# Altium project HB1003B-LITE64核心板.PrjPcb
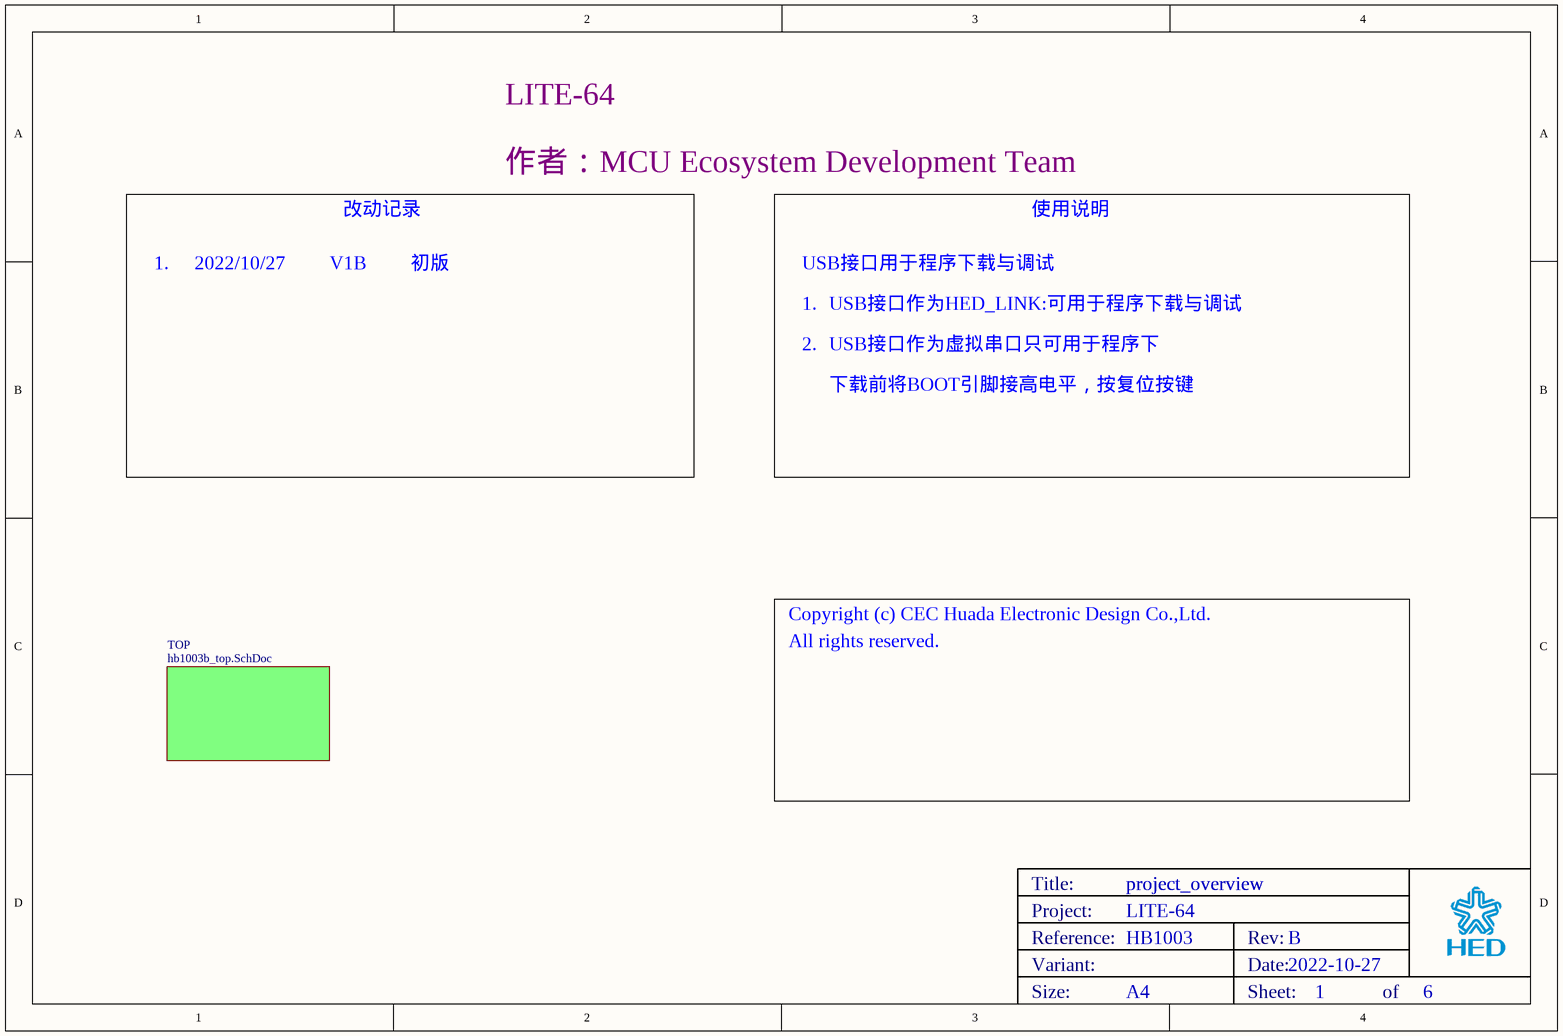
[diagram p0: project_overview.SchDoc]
Board_Assembly_Revision: 01; Board_Name: LITE-64; Board_PCB_Revision: B; Board_Reference: HB1003
6 sheets, 120 parts. Net scope: global (net labels, ports and power ports of the same name join across sheets).
Board file: hb1003b.PcbDoc
Sheets:
  project_overview.SchDoc
    TOP = hb1003b_top.SchDoc
      hed_link = hed_link.SchDoc
      arduino_extension_interfaces = arduino_extension_interfaces.SchDoc
      MCU = mcu.SchDoc
      power = power.SchDoc

## Sheet project_overview.SchDoc: project_overview
size A4; Date: 2022-10-27; DrawnBy: liuchao; SheetNumber: 1; SheetTotal: 6

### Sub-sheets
TOP = hb1003b_top.SchDoc: no entries

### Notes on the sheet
- 作者：MCU Ecosystem Development Team
- 改动记录
- 使用说明
- 1.
- 2022/10/27
- V1B
- 初版
- USB接口用于程序下载与调试
- USB接口作为HED_LINK:可用于程序下载与调试
- 2.
- USB接口作为虚拟串口只可用于程序下
- 下载前将BOOT引脚接高电平，按复位按键
- Copyright (c) CEC Huada Electronic Design Co.,Ltd.
- All rights reserved.

## Sheet hb1003b_top.SchDoc: top
size A4; Date: 2022-10-27; DrawnBy: liuchao; SheetNumber: 2; SheetTotal: 6
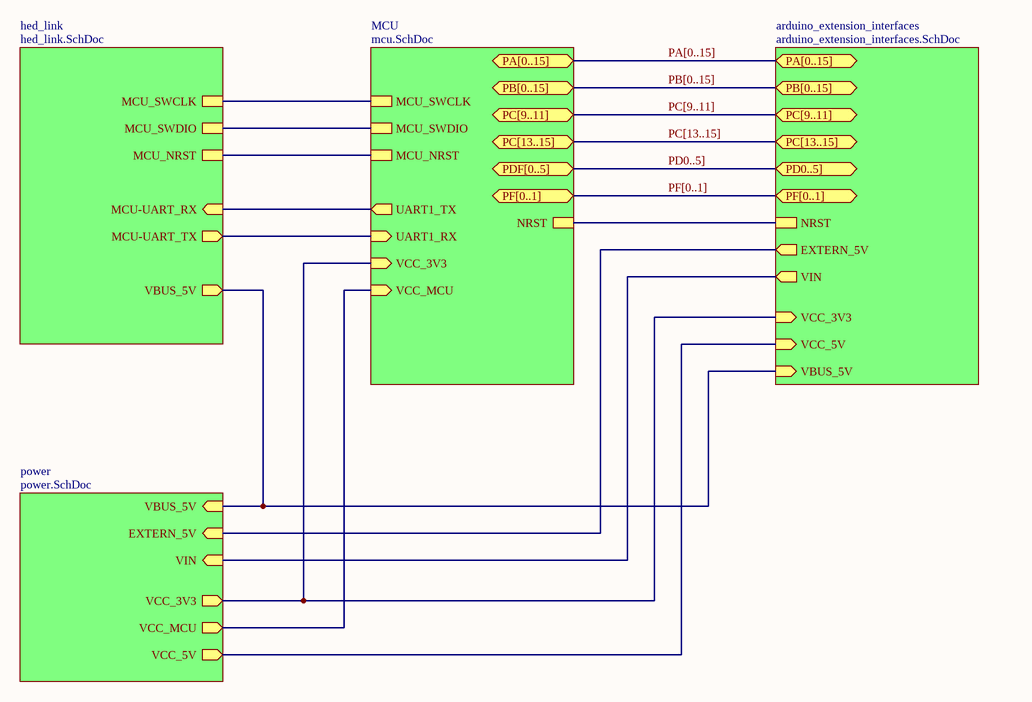
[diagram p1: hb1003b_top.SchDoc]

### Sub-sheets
arduino_extension_interfaces = arduino_extension_interfaces.SchDoc: NRST, VBUS_5V (in), EXTERN_5V (out), VIN (out), VCC_3V3 (in), VCC_5V (in)
hed_link = hed_link.SchDoc: MCU_SWDIO, MCU_SWCLK, MCU_NRST, MCU-UART_RX (in), MCU-UART_TX (out), VBUS_5V (out)
MCU = mcu.SchDoc: UART1_RX (in), UART1_TX (out), MCU_SWCLK, MCU_SWDIO, MCU_NRST, VCC_3V3 (in), VCC_MCU (in), NRST
power = power.SchDoc: VCC_MCU (out), VBUS_5V (in), EXTERN_5V (in), VIN (in), VCC_3V3 (out), VCC_5V (out)

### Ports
PA[0..15], PB[0..15], PC[9..11], PC[13..15], PD0..5], PDF[0..5], PF[0..1]

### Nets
(unnamed): sheet hed_link/MCU_SWDIO, sheet MCU/MCU_SWDIO
(unnamed): sheet hed_link/MCU_SWCLK, sheet MCU/MCU_SWCLK  [a separate net that carries the same name]
(unnamed): sheet hed_link/MCU_NRST, sheet MCU/MCU_NRST  [a separate net that carries the same name]
(unnamed): sheet hed_link/MCU-UART_RX, sheet MCU/UART1_TX  [a separate net that carries the same name]
(unnamed): sheet hed_link/MCU-UART_TX, sheet MCU/UART1_RX  [a separate net that carries the same name]
(unnamed): sheet hed_link/VBUS_5V, sheet arduino_extension_interfaces/VBUS_5V, sheet power/VBUS_5V  [a separate net that carries the same name]
(unnamed): sheet arduino_extension_interfaces/NRST, sheet MCU/NRST  [a separate net that carries the same name]
(unnamed): sheet arduino_extension_interfaces/EXTERN_5V, sheet power/EXTERN_5V  [a separate net that carries the same name]
(unnamed): sheet arduino_extension_interfaces/VIN, sheet power/VIN  [a separate net that carries the same name]
(unnamed): sheet arduino_extension_interfaces/VCC_3V3, sheet MCU/VCC_3V3, sheet power/VCC_3V3  [a separate net that carries the same name]
(unnamed): sheet arduino_extension_interfaces/VCC_5V, sheet power/VCC_5V  [a separate net that carries the same name]
(unnamed): sheet MCU/VCC_MCU, sheet power/VCC_MCU  [a separate net that carries the same name]

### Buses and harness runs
bus PA[0..15] = port PA[0..15]
bus PB[0..15] = port PB[0..15]
bus PC[9..11] = port PC[9..11]
bus PC[13..15] = port PC[13..15]
bus PD0..5] = port PD0..5] = port PDF[0..5]
bus PF[0..1] = port PF[0..1]

## Sheet hed_link.SchDoc: HED_Link
size A4; Date: 2022-10-27; DrawnBy: liuchao; SheetNumber: 6; SheetTotal: 6
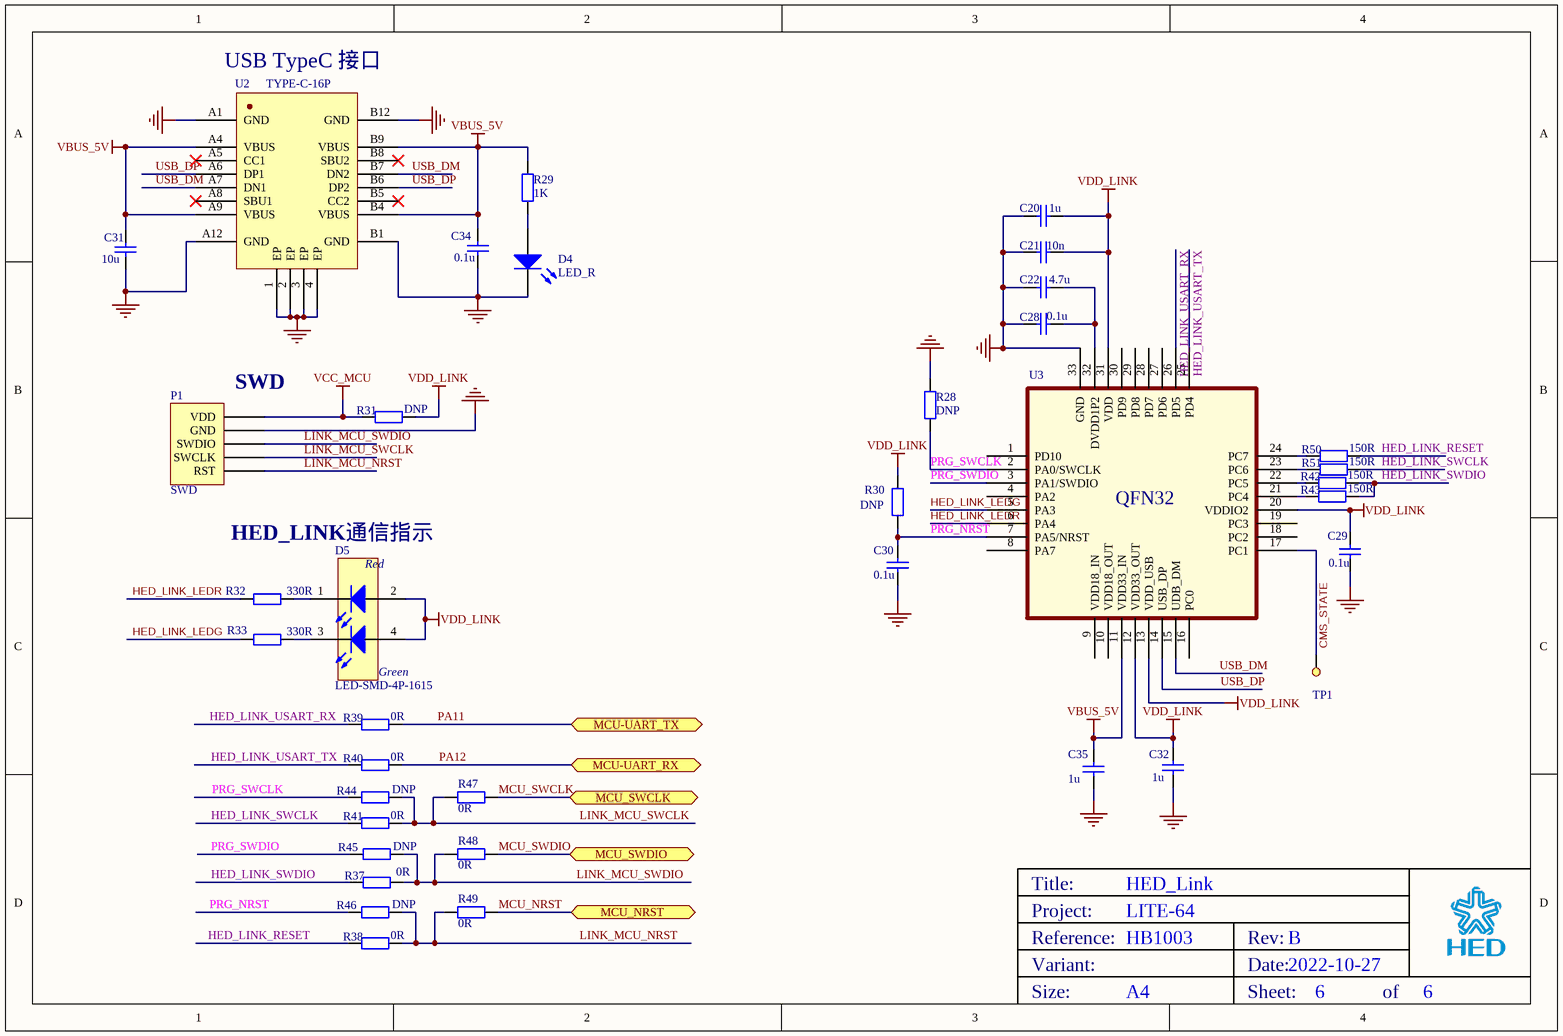
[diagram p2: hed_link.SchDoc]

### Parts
C20  1u  [0603]
C21  10n  [0603]
C22  4.7u  [0603]
C28  0.1u  [0603]
C29  0.1u  [0603]
C30  0.1u  [0603]
C31  10u  [0603]
C32  1u  [0603]
C34  0.1u  [0603]
C35  1u  [0603]
D4  LED_R  [0603 - p]
D5  Manufacturer_Part_Number: LED-SMD-4P-1615  [LED-SMD_4P_1615]  (hidden comment: LD_BICOLOR_CMS)
P1  SWD  [HED_5_4_2.5]
R28  DNP  [0603]
R29  1K  [0603]
R30  DNP  [0603]
R31  DNP  [0603]
R32  330R  [0603]
R33  330R  [0603]
R37  0R  [0603]
R38  0R  [0603]
R39  0R  [0603]
R40  0R  [0603]
R41  0R  [0603]
R42  150R  [0603]
R43  150R  [0603]
R44  DNP  [0603]
R45  DNP  [0603]
R46  DNP  [0603]
R47  0R  [0603]
R48  0R  [0603]
R49  0R  [0603]
R50  150R  [0603]
R51  150R  [0603]
TP1  TEST_POINT  [TEST_POINT]  (value not drawn)
U2  TYPE-C-16P  [HED-KH-TYPE-C-16P]
U3  MCU  [HED-QFN-32_5x5x05P]  (value not drawn)

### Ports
MCU-UART_RX (bidir), MCU-UART_TX (bidir), MCU_NRST, MCU_SWCLK, MCU_SWDIO

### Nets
GND: C20.1 C21.1 C22.1 C28.1 C29.2 C30.2 C31.1 C32.2 C34.1 C35.2 D4.2(K) P1.2(GND) R28.2 U2.1(EP) U2.2(EP) U2.3(EP) U2.4(EP) U2.A1(GND) U2.A12(GND) U2.B1(GND) U2.B12(GND) U3.33(GND)
VBUS_5V: C31.2 C34.2 C35.1 R29.1 U2.A4(VBUS) U2.A9(VBUS) U2.B4(VBUS) U2.B9(VBUS) U3.11(VDD33_IN)
VCC_MCU: P1.1(VDD) R31.1
VDD_LINK: C20.2 C21.2 C29.1 C32.1 D5.2(RED_cathode) D5.4(YellowGreen_anode) R30.1 R31.2 U3.12(VDD33_OUT) U3.13(VDD_USB) U3.20(VDDIO2) U3.31(VDD)
CMS_STATE: TP1.1 U3.17(PC1)
HED_LINK_LEDG: R33.1 U3.5(PA3)
HED_LINK_LEDR: R32.1 U3.6(PA4)
HED_LINK_RESET: R38.1 R50.2
HED_LINK_SWCLK: R41.1 R51.2
HED_LINK_SWDIO: R37.1 R42.2 R43.2
HED_LINK_USART_RX: R39.1 U3.26(PD5)
HED_LINK_USART_TX: R40.1 U3.25(PD4)
LINK_MCU_NRST: P1.5(RST) R38.2 R46.2 R49.2
LINK_MCU_SWCLK: P1.4(SWCLK) R41.2 R44.2 R47.2
LINK_MCU_SWDIO: P1.3(SWDIO) R37.2 R45.2 R48.2
MCU_NRST: R49.1 ; port MCU_NRST
MCU_SWCLK: R47.1 ; port MCU_SWCLK
MCU_SWDIO: R48.1 ; port MCU_SWDIO
PA11: R39.2 ; port MCU-UART_TX
PA12: R40.2 ; port MCU-UART_RX
PRG_NRST: C30.1 R30.2 R46.1 U3.7(PA5/NRST)
PRG_SWCLK: R28.1 R44.1 U3.2(PA0/SWCLK)
PRG_SWDIO: R45.1 U3.3(PA1/SWDIO)
USB_DM: U2.A7(DN1) U2.B7(DN2) U3.15(UDB_DM)
USB_DP: U2.A6(DP1) U2.B6(DP2) U3.14(USB_DP)
NetC22_2: C22.2 C28.2 U3.32(DVDD1P2)
NetD4_1: D4.1(A) R29.2
NetD5_1: D5.1(Red_anode) R32.2
NetD5_3: D5.3(YellowGreen_cathode) R33.2
NetR42_1: R42.1 U3.22(PC5)
NetR43_1: R43.1 U3.21(PC4)
NetR50_1: R50.1 U3.24(PC7)
NetR51_1: R51.1 U3.23(PC6)

Not connected (* = marked no-connect by the designer): U2 A5(CC1)* A8(SBU1)* B5(CC2)* B8(SBU2)*; U3 1(PD10) 4(PA2) 8(PA7) 9(VDD18_IN) 10(VDD18_OUT) 16(PC0) 18(PC2) 19(PC3) 27(PD6) 28(PD7) 29(PD8) 30(PD9)

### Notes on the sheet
- (near U2) USB TypeC 接口
- (near P1) SWD
- HED_LINK通信指示

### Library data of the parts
C20-C22 C28-C30 C32 C35 = MCD-00211: Capacitor, MLCC, 100nF, 16V, X7R, 10%, 0603, T=0,8mm; Manufacturer_Part_Number: CC0603KRX7R7BB104; Manufacturer: YAGEO; Provided_By: Subcon; Initial_Board_Reference: mb1319
C31 = 0603 4.7uF 10% 16V: 贴片电容
C34 = 0603 100nF 10% 50V: 贴片电容
D4 = LED3: Typical BLUE SiC LED; sold/unsold: sold
D5 = LD_BICOLOR_CMS: LED Bicolor; Internal_Part_Number: MCD-00051; Part_Type: Display; Manufacturer: AVAGO TECHNOLOGIES; Alternate_Manufacturer_Part_Number: LE-RGW35280; Alternate_Manufacturer: EVERLUCK; ECCN_US: EAR99; ECCN_EU: NEC; Provided_By: Subcon; Initial_Board_Reference: mb1274
R28 R44-R49 = Res: 贴片电阻; Value: 1K
R29 = Res2: 贴片电阻
R30-R33 R37-R43 R50 R51 = Res2: 贴片电阻; Value: 1K
U2 = KH-TYPE-C-16P: TYPE-C USB接口
U3 = CIU98-H

## Sheet arduino_extension_interfaces.SchDoc: arduino interface
size A4; Date: 2022-10-27; DrawnBy: liuchao; SheetNumber: 5; SheetTotal: 6
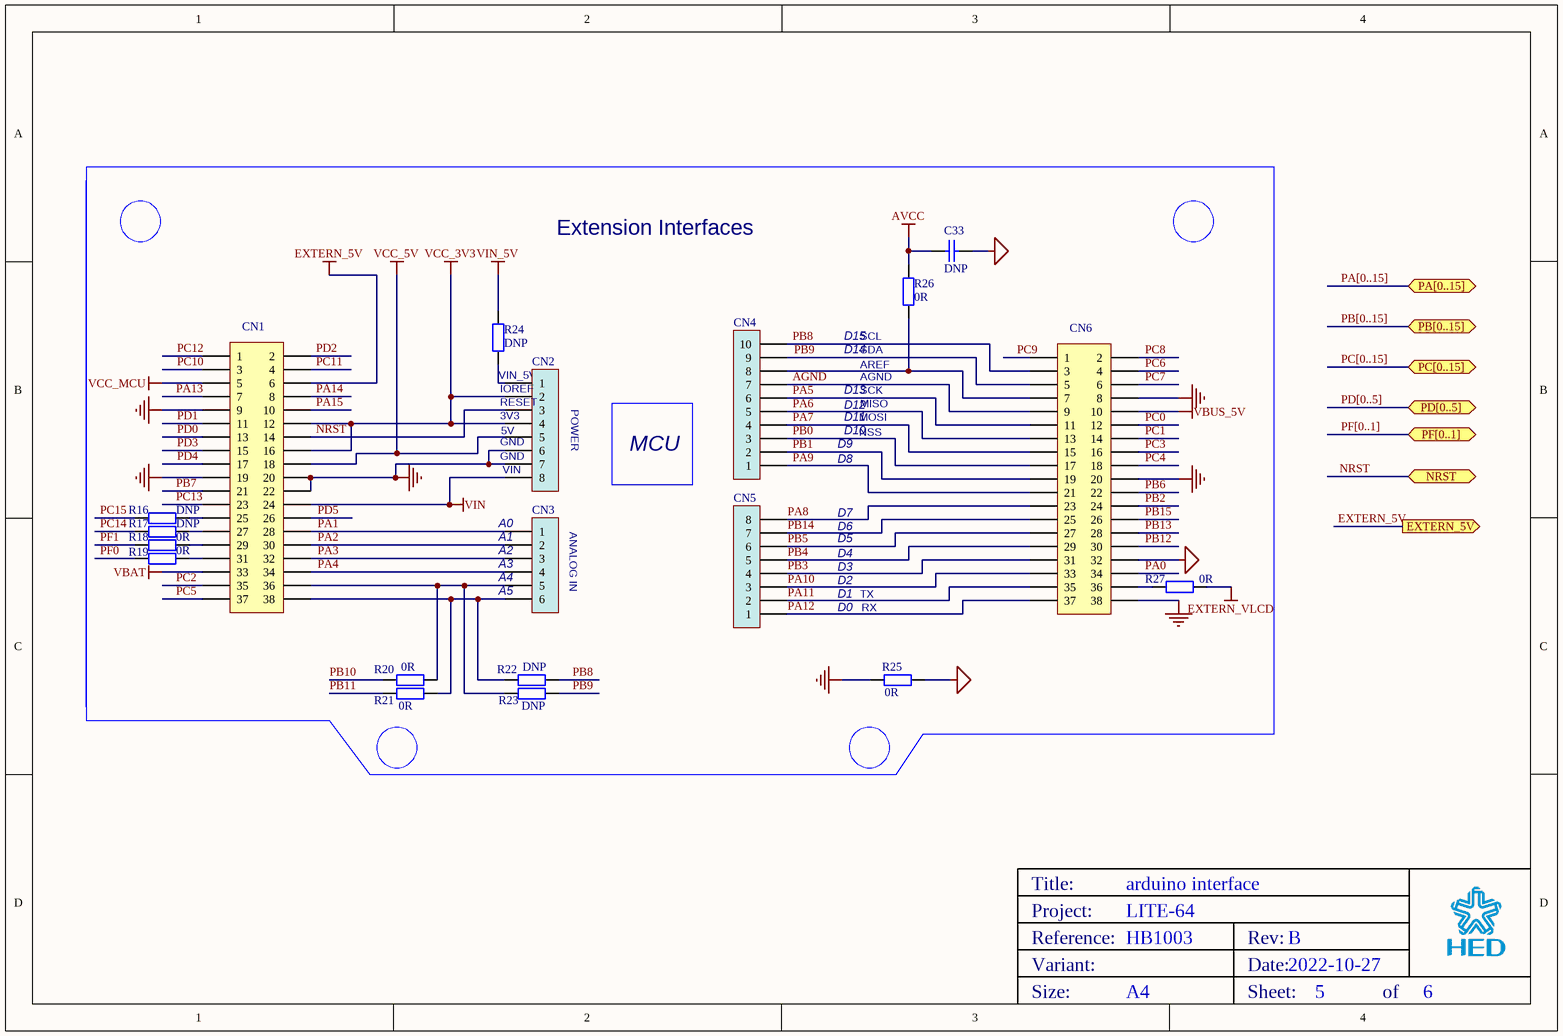
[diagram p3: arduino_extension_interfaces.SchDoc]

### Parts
C33  DNP  [0603]
CN1  Header 23x2  [HEADER_1X19_2.54]  (value not drawn)
CN2  Socket 8x1  [HEADER_1X8_2.54]  (value not drawn)
CN3  Socket 6x1  [HEADER_1X6-2.54]  (value not drawn)
CN4  Socket 10x1  [HEADER_1X10_2.54]  (value not drawn)
CN5  Socket 8x1  [HEADER_1X8_2.54]  (value not drawn)
CN6  Header 23x2  [HEADER_1X19_2.54]  (value not drawn)
R16  DNP  [0603]
R17  DNP  [0603]
R18  0R  [0603]
R19  0R  [0603]
R20  0R  [0603]
R21  0R  [0603]
R22  DNP  [0603]
R23  DNP  [0603]
R24  DNP  [0603]
R25  0R  [0603]
R26  0R  [0603]
R27  0R  [0603]

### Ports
EXTERN_5V (out), NRST, PA[0..15] (bidir), PB[0..15] (bidir), PC[0..15] (bidir), PD[0..5], PF[0..1] (bidir)

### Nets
AGND: C33.1 CN4.7 CN6.9 CN6.32 R25.1
EXTERN_5V: CN1.6 ; port EXTERN_5V
EXTERN_VLCD: R27.1
GND: CN1.9 CN1.19 CN1.20 CN1.22 CN2.6 CN2.7 CN6.8 CN6.20 CN6.38 R25.2
PA0: C33.2 CN6.34 R26.1  [also labelled AVCC]
VBAT: CN1.33
VBUS_5V: CN6.10
VCC_3V3: CN1.12 CN1.16 CN2.2 CN2.4
VCC_5V: CN1.18 CN2.5
VCC_MCU: CN1.5
VIN: CN1.24 CN2.8
VIN_5V: R24.1
NRST: CN1.14 CN2.3 ; port NRST
PA1: CN1.28 CN3.1
PA2: CN1.30 CN3.2
PA3: CN1.32 CN3.3
PA4: CN1.34 CN3.4
PA5: CN4.6 CN6.11
PA6: CN4.5 CN6.13
PA7: CN4.4 CN6.15
PA8: CN5.8 CN6.23
PA9: CN4.1 CN6.21
PA10: CN5.3 CN6.33
PA11: CN5.2 CN6.35
PA12: CN5.1 CN6.37
PA13: CN1.7
PA14: CN1.8
PA15: CN1.10
PB0: CN4.3 CN6.17
PB1: CN4.2 CN6.19
PB2: CN6.24
PB3: CN5.4 CN6.31
PB4: CN5.5 CN6.29
PB5: CN5.6 CN6.27
PB6: CN6.22
PB7: CN1.21
PB8: CN4.10 CN6.3 R22.1
PB9: CN4.9 CN6.5 R23.1
PB10: R20.2
PB11: R21.2
PB12: CN6.30
PB13: CN6.28
PB14: CN5.7 CN6.25
PB15: CN6.26
PC0: CN6.12
PC1: CN6.14
PC2: CN1.35
PC3: CN6.16
PC4: CN6.18
PC5: CN1.37
PC6: CN6.4
PC7: CN6.6
PC8: CN6.2
PC9: CN6.1
PC10: CN1.3
PC11: CN1.4
PC12: CN1.1
PC13: CN1.23
PC14: R17.2
PC15: R16.2
PD0: CN1.13
PD1: CN1.11
PD2: CN1.2
PD3: CN1.15
PD4: CN1.17
PD5: CN1.26
PF0: R19.2
PF1: R18.2
NetCN1_25: CN1.25 R16.1
NetCN1_27: CN1.27 R17.1
NetCN1_29: CN1.29 R18.1
NetCN1_31: CN1.31 R19.1
NetCN1_36: CN1.36 CN3.5 R20.1 R23.2
NetCN1_38: CN1.38 CN3.6 R21.1 R22.2
NetCN2_1: CN2.1 R24.2
NetCN4_8: CN4.8 CN6.7 R26.2
NetCN6_36: CN6.36 R27.2

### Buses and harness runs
bus PA[0..15] = port PA[0..15]
bus PB[0..15] = port PB[0..15]
bus PC[0..15] = port PC[0..15]
bus PD[0..5] = port PD[0..5]
bus PF[0..1] = port PF[0..1]

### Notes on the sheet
- Extension Interfaces
- (near CN2) VIN_5V
- D14
- D15
- (near R26) SDA
- (near R26) SCL
- AREF
- AGND
- (near CN2) IOREF
- (near CN2) 3V3
- (near CN2) GND
- (near CN2) RESET
- (near CN2) 5V
- (near CN2) POWER
- D9
- D10
- D13
- D12
- D11
- MOSI
- NSS
- MISO
- SCK
- (near CN2) VIN
- MCU
- D7
- D8
- (near CN3) A0
- (near CN3) A1
- (near CN3) A2
- (near CN3) A3
- (near CN3) A4
- (near CN3) ANALOG IN
- D2
- D4
- D3
- D5
- D6
- (near CN3) A5
- D0
- D1
- TX
- RX

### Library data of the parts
C33 = MCD-00211: as C20 on sheet hed_link
CN1 CN6 = Header 19x2: Header, 19x2, 2,54mm, VR, TH, Height 5.84mm/10.16mm; Internal_Part_Number: MCD-00213; Manufacturer: SAMTEC; Part_Type: Connector; Manufacturer_Part_Number: TSW-119-09-x-D1; Provided_By: Subcon; Initial_Board_Reference: mb1319
CN2 = MCD-00261: Socket, 8x1, 2.54mm, VR, TH, Height 8.51mm/10mm; Manufacturer_Part_Number: SSW-108-03-x-S; Manufacturer: SAMTEC; Part_Type: Connector; Provided_By: Subcon; Initial_Board_Reference: mb1319
CN3 = MCD-00260: Socket, 6x1, 2.54mm, VR, TH, Height 8.51mm/10mm; Part_Type: Connector; Manufacturer_Part_Number: SSW-106-03-x-S; Manufacturer: SAMTEC; Provided_By: Subcon; Initial_Board_Reference: mb1319
CN4 = MCD-00262: Socket, 10x1, 2.54mm, VR, TH, Height 8.51mm/10mm; Manufacturer_Part_Number: SSW-110-03-x-S; Manufacturer: SAMTEC; Part_Type: Connector; Provided_By: Subcon; Initial_Board_Reference: mb1319
CN5 = MCD-00261: Socket, 8x1, 2.54mm, VR, TH, Height 8.51mm/10mm; Part_Type: Connector; Manufacturer_Part_Number: SSW-108-03-x-S; Manufacturer: SAMTEC; Provided_By: Subcon; Initial_Board_Reference: mb1319
R16-R27 = Res2: 贴片电阻; Value: 1K

## Sheet mcu.SchDoc: MCU
size A4; Date: 2022-10-27; DrawnBy: liuchao; SheetNumber: 3; SheetTotal: 6
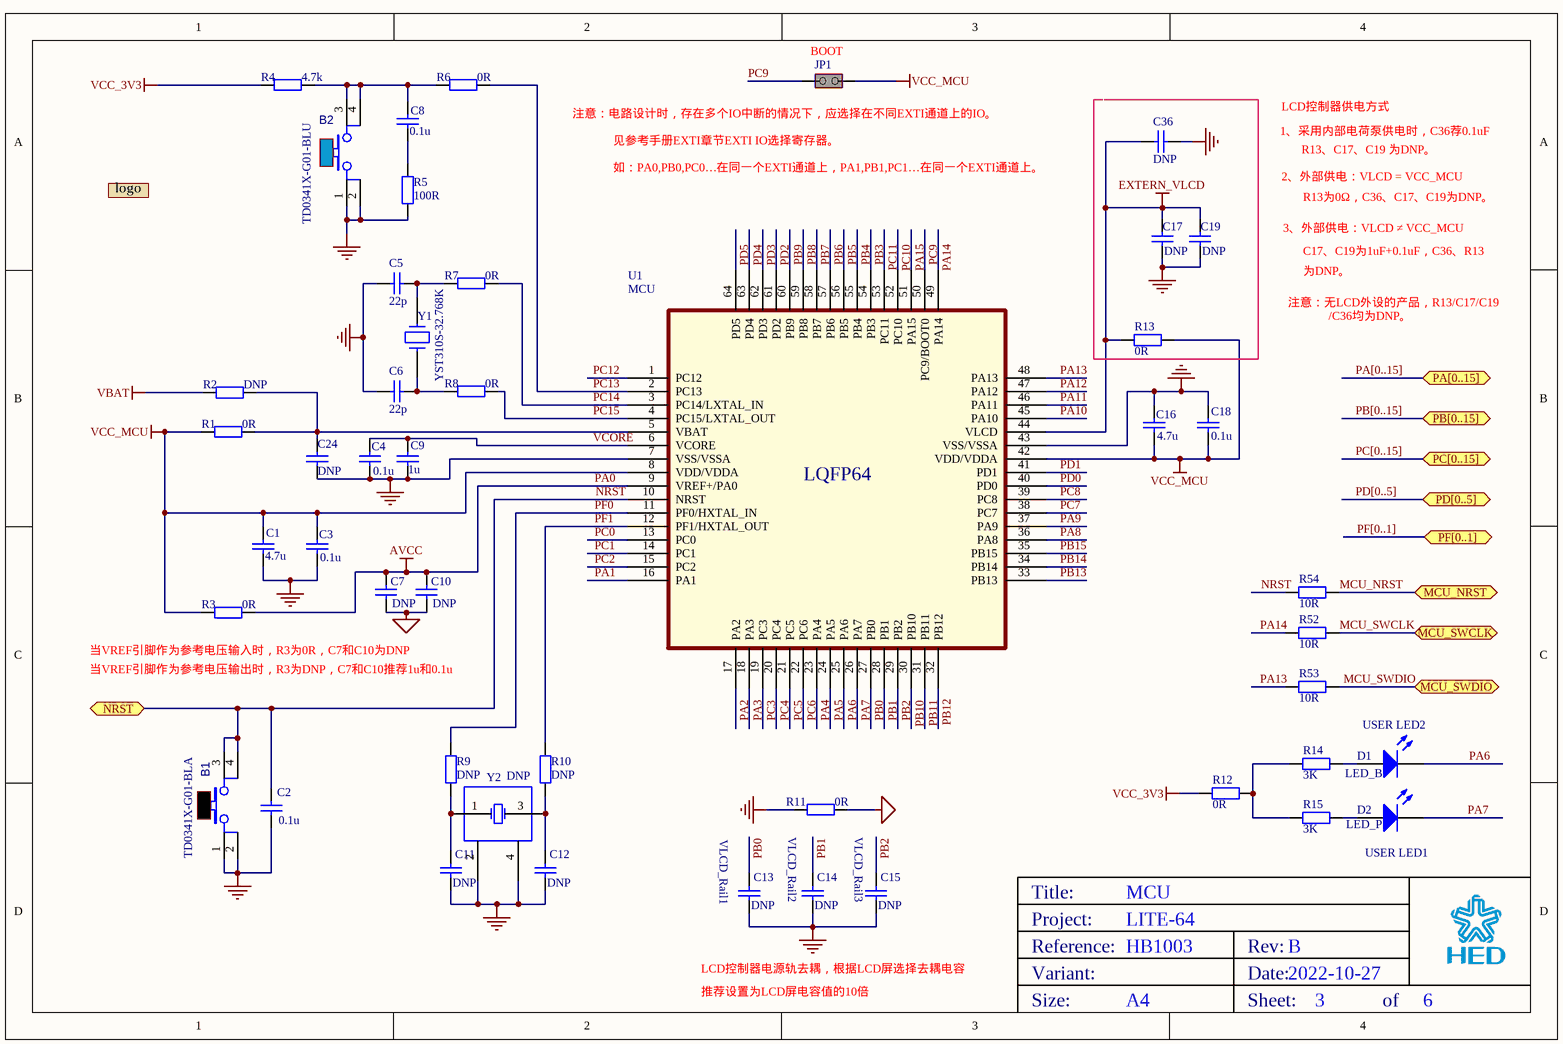
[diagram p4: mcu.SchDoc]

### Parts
B1  Manufacturer_Part_Number: TD0341X-G01-BLA  [SWI_WEALTHMETAL_TD-0341_4P_BLACK]  (hidden comment: SW-PUSH-CMS_BLACK)
B2  Manufacturer_Part_Number: TD0341X-G01-BLU  [SWI_WEALTHMETAL_TD-0341_4P_BLUE]  (hidden comment: SW-PUSH-CMS_BLUE)
C1  4.7u  [0603]
C2  0.1u  [0603]
C3  0.1u  [0603]
C4  0.1u  [0603]
C5  22p  [0603]
C6  22p  [0603]
C7  DNP  [0603]
C8  0.1u  [0603]
C9  1u  [0603]
C10  DNP  [0603]
C11  DNP  [0603]
C12  DNP  [0603]
C13  DNP  [0603]
C14  DNP  [0603]
C15  DNP  [0603]
C16  4.7u  [0603]
C17  DNP  [0603]
C18  0.1u  [0603]
C19  DNP  [0603]
C24  DNP  [0603]
C36  DNP  [0603]
D1  LED_B  [0603 - p]
D2  LED_P  [0603 - p]
JP1  Shunt Fitted  [HEADER_1X2_2.54]  (value not drawn)
logo1  logo  [华大电子LOGO]  (value not drawn)
R1  0R  [0603]
R2  DNP  [0603]
R3  0R  [0603]
R4  4.7k  [0603]
R5  100R  [0603]
R6  0R  [0603]
R7  0R  [0603]
R8  0R  [0603]
R9  DNP  [0603]
R10  DNP  [0603]
R11  0R  [0603]
R12  0R  [0603]
R13  0R  [0603]
R14  3K  [0603]
R15  3K  [0603]
R52  10R  [0603]
R53  10R  [0603]
R54  10R  [0603]
U1  MCU  [LQFP_64N_7X7]
Y1  value YST310S-32.768K  [CRY_3215SA_2P]  (hidden comment: YST310S)
Y2  DNP  [3.2*2.5*0.7 OSC]

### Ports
MCU_NRST, MCU_SWCLK, MCU_SWDIO, NRST, PA[0..15] (bidir), PB[0..15] (bidir), PC[0..15] (bidir), PD[0..5], PF[0..1] (bidir)

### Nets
AGND: C7.1 C10.1 R11.1
EXTERN_VLCD: C17.1 C19.1 C36.2 R13.1 U1.44(VLCD)
GND: B1.1 B1.2 B2.1 B2.2 C1.1 C2.2 C3.1 C4.2 C5.1 C6.1 C9.2 C11.2 C12.2 C13.2 C14.2 C15.2 C16.2 C17.2 C18.2 C19.2 C24.1 C36.1 R5.2 R11.2 U1.7(VSS/VSSA) U1.43(VSS/VSSA) Y2.2(OSC2) Y2.4(OSC4)
PA0: C7.2 C10.2 R3.1 U1.9(VREF+/PA0)  [also labelled AVCC]
VBAT: R2.2
VCC_3V3: R4.2 R12.2
VCC_MCU: C1.2 C3.2 C16.1 C18.1 JP1.2(NO) R1.2 R3.2 R13.2 U1.8(VDD/VDDA) U1.42(VDD/VDDA)
MCU_NRST: R54.1 ; port MCU_NRST
MCU_SWCLK: R52.1 ; port MCU_SWCLK
MCU_SWDIO: R53.1 ; port MCU_SWDIO
NRST: B1.3 B1.4 C2.1 R54.2 U1.10(NRST) ; port NRST
PA1: U1.16(PA1)
PA2: U1.17(PA2)
PA3: U1.18(PA3)
PA4: U1.23(PA4)
PA5: U1.24(PA5)
PA6: D1.2(K) U1.25(PA6)
PA7: D2.2(K) U1.26(PA7)
PA8: U1.36(PA8)
PA9: U1.37(PA9)
PA10: U1.45(PA10)
PA11: U1.46(PA11)
PA12: U1.47(PA12)
PA13: R53.2 U1.48(PA13)
PA14: R52.2 U1.49(PA14)
PA15: U1.51(PA15)
PB0: C13.1 U1.27(PB0)
PB1: C14.1 U1.28(PB1)
PB2: C15.1 U1.29(PB2)
PB3: U1.54(PB3)
PB4: U1.55(PB4)
PB5: U1.56(PB5)
PB6: U1.57(PB6)
PB7: U1.58(PB7)
PB8: U1.59(PB8)
PB9: U1.60(PB9)
PB10: U1.30(PB10)
PB11: U1.31(PB11)
PB12: U1.32(PB12)
PB13: U1.33(PB13)
PB14: U1.34(PB14)
PB15: U1.35(PB15)
PC0: U1.13(PC0)
PC1: U1.14(PC1)
PC2: U1.15(PC2)
PC3: U1.19(PC3)
PC4: U1.20(PC4)
PC5: U1.21(PC5)
PC6: U1.22(PC6)
PC7: U1.38(PC7)
PC8: U1.39(PC8)
PC9: JP1.1(COMMON) U1.50(PC9/BOOT0)
PC10: U1.52(PC10)
PC11: U1.53(PC11)
PC12: U1.1(PC12)
PC13: R6.1 U1.2(PC13)
PC14: R7.1 U1.3(PC14/LXTAL_IN)
PC15: R8.1 U1.4(PC15/LXTAL_OUT)
PD0: U1.40(PD0)
PD1: U1.41(PD1)
PD2: U1.61(PD2)
PD3: U1.62(PD3)
PD4: U1.63(PD4)
PD5: U1.64(PD5)
PF0: R9.2 U1.11(PF0/HXTAL_IN)
PF1: R10.2 U1.12(PF1/HXTAL_OUT)
VCORE: C4.1 C9.1 U1.6(VCORE)
NetB2_3: B2.3 B2.4 C8.2 R4.1 R6.2
NetC5_2: C5.2 R7.2 Y1.1
NetC6_2: C6.2 R8.2 Y1.2
NetC8_1: C8.1 R5.1
NetC11_1: C11.1 R9.1 Y2.1(OSC1)
NetC12_1: C12.1 R10.1 Y2.3(OSC3)
NetC24_2: C24.2 R1.1 R2.1 U1.5(VBAT)
NetD1_1: D1.1(A) R14.1
NetD2_1: D2.1(A) R15.1
NetR12_1: R12.1 R14.2 R15.2

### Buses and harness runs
bus PA[0..15] = port PA[0..15]
bus PB[0..15] = port PB[0..15]
bus PC[0..15] = port PC[0..15]
bus PD[0..5] = port PD[0..5]
bus PF[0..1] = port PF[0..1]

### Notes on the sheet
- (near JP1) BOOT
- (near JP1) 注意：电路设计时，存在多个IO中断的情况下，应选择在不同EXTI通道上的IO。
- LCD控制器供电方式
- 如：PA0,PB0,PC0…在同一个EXTI通道上，PA1,PB1,PC1…在同一个EXTI通道上。
- 见参考手册EXTI章节EXTI IO选择寄存器。
- 1、采用内部电荷泵供电时，C36荐0.1uF
- 2、外部供电：VLCD = VCC_MCU
- R13、C17、C19 为DNP。
- 3、外部供电：VLCD ≠ VCC_MCU
- C17、C19为1uF+0.1uF，C36、R13
- R13为0Ω，C36、C17、C19为DNP。
- 注意：无LCD外设的产品，R13/C17/C19
- 为DNP。
- /C36均为DNP。
- (near R3) 当VREF引脚作为参考电压输入时，R3为0R，C7和C10为DNP
- (near R3) 当VREF引脚作为参考电压输出时，R3为DNP，C7和C10推荐1u和0.1u
- USER LED2
- (near C13) VLCD_Rail1
- (near C14) VLCD_Rail2
- (near C15) VLCD_Rail3
- USER LED1
- LCD控制器电源轨去耦，根据LCD屏选择去耦电容
- 推荐设置为LCD屏电容值的10倍

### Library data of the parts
B1 = MCD-00001: Non-Open Push-Button 0.1A 24V; Part_Type: Misc; Manufacturer: WEALTHMETAL; Value: SW_BLACK; Provided_By: Subcon; Initial_Board_Reference: mb1274
B2 = MCD-00002: Non-Open Push-Button 0.1A 24V; Part_Type: Misc; Manufacturer: WEALTHMETAL; Value: SW_BLUE; Provided_By: Subcon; Initial_Board_Reference: mb1274
C1 C13-C17 C19 C36 = MCD-00009: Capacitor, MLCC, 4.7uF, 16V, X5R, 10%, 0603, T=0.8mm; Manufacturer_Part_Number: CC0603KRX5R7BB475; Manufacturer: YAGEO; Provided_By: subcon; Initial_Board_Reference: mb1274
C2-C4 C7 C9 C10 C18 = MCD-00211: as C20 on sheet hed_link
C5 C6 = MCD-00666: Capacitor,5.6pF,0.1pF,16V,NPO,0603; Manufacturer_Part_Number: CC0603BRNPO7BN5R6; Manufacturer: YAGEO; Provided_By: Subcon; Initial_Board_Reference: MB1360
C8 = MCD-00211: 贴片电容; Manufacturer_Part_Number: CC0603KRX7R7BB104; Manufacturer: YAGEO; Provided_By: Subcon; Initial_Board_Reference: mb1319
C11 C12 = MCD-00009: 33p贴片电容; Manufacturer_Part_Number: CC0603KRX5R7BB475; Manufacturer: YAGEO; Provided_By: subcon; Initial_Board_Reference: mb1274
C24 = MCD-00014: Capacitor, MLCC, 10uF, 25V, X5R, 10%, 0805, T=0,85mm; Manufacturer_Part_Number: CC0805KRX5R8BB106; Manufacturer: YAGEO; Provided_By: Subcon; Initial_Board_Reference: mb1274
D1 D2 = LED1: Typical RED GaAs LED
JP1 = MCD-00683: Header, 2x1, 2,54mm, VR, TH, Height 5.84mm/2.54mm - Shunt Fitted by default; Part_Type: Connector; Manufacturer_Part_Number: TSW-102-07-x-S; Manufacturer: SAMTEC; Provided_By: Subcon; Initial_Board_Reference: MB1331
R1-R15 = Res2: 贴片电阻; Value: 1K
R52-R54 = Res: 贴片电阻; Value: 1K
U1 = LQFP64
Y1 = MCD-00091: 32.768k无源晶振; Part_Type: Crystal_Osc; Manufacturer_Part_Number: NX3215SA 32.768KHz EXS00A-MU00525; Manufacturer: NDK; ECCN_US: EAR99; ECCN_EU: NEC; Provided_By: STM; Initial_Board_Reference: mb1274
Y2 = XTAL_4: 'X32258MSB4SI 无源晶振

## Sheet power.SchDoc: power
size A4; Date: 2022-10-27; DrawnBy: liuchao; SheetNumber: 4; SheetTotal: 6
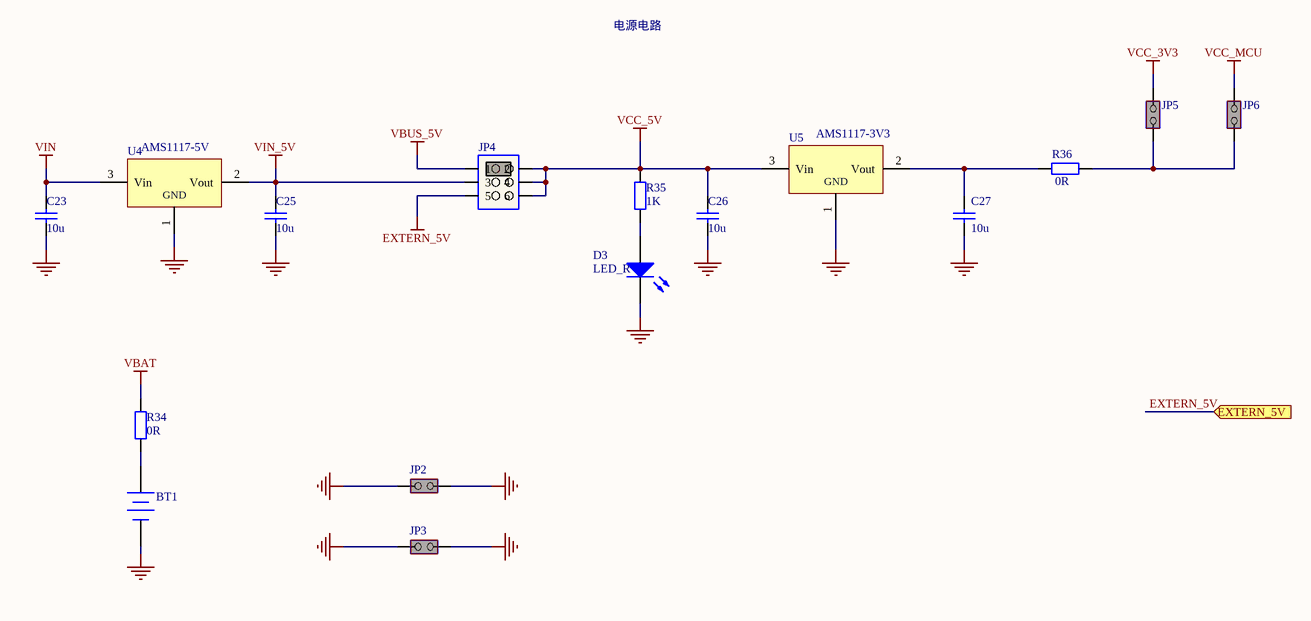
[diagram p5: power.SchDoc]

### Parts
BT1  (no value)  [CR1220]
C23  10u  [0603]
C25  10u  [0603]
C26  10u  [0603]
C27  10u  [0603]
D3  LED_R  [0603 - P]
JP2  Shunt Fitted  [CON_SAMTEC_TSW-102-07-G-S]  (value not drawn)
JP3  Shunt Fitted  [CON_SAMTEC_TSW-102-07-G-S]  (value not drawn)
JP4  Shunt Fitted 1-2  [HEADER_2X3_2.54]  (value not drawn)
JP5  Shunt Fitted  [HEADER_1X2_2.54]  (value not drawn)
JP6  Shunt Fitted  [HEADER_1X2_2.54]  (value not drawn)
R34  0R  [0603]
R35  1K  [0603]
R36  0R  [0603]
U4  AMS1117-5V  [SOT223]
U5  AMS1117-3V3  [SOT223]

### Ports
EXTERN_5V (in)

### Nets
EXTERN_5V: JP4.5 ; port EXTERN_5V
GND: BT1.2(-) C23.1 C25.1 C26.1 C27.1 D3.2(K) JP2.1(COMMON) JP2.2(NO) JP3.1(COMMON) JP3.2(NO) U4.1(GND) U5.1(GND)
VBAT: R34.1
VBUS_5V: JP4.1
VCC_3V3: JP5.1(COMMON)
VCC_5V: C26.2 JP4.2 JP4.4 JP4.6 R35.2 U5.3(Vin)
VCC_MCU: JP6.1(COMMON)
VIN: C23.2 U4.3(Vin)
VIN_5V: C25.2 JP4.3 U4.2(Vout)
NetBT1_1: BT1.1(+) R34.2
NetC27_2: C27.2 R36.2 U5.2(Vout)
NetD3_1: D3.1(A) R35.1
NetJP5_2: JP5.2(NO) JP6.2(NO) R36.1

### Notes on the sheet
- 电源电路

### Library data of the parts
BT1 = Battery: Multicell Battery
C23 C25-C27 = MCD-00014: as C24 on sheet mcu
D3 = LED1: Typical RED GaAs LED
JP2 JP3 JP5 JP6 = MCD-00683: as JP1 on sheet mcu
JP4 = Jumper_Header 4x2 Fitted 1-2: Header, 4x2, 2,54mm, VR, TH, Height 5.84mm/2.54mm - Shunt Fitted 1-2; Internal_Part_Number: MCD-00686; Part_Type: Connector; Manufacturer_Part_Number: TSW-104-07-x-D; Manufacturer: SAMTEC; Provided_By: Subcon; Initial_Board_Reference: MB1331
R34 R36 = Res2: 贴片电阻; Value: 1K
R35 = Res2: 贴片电阻
U4 U5 = AMS1117: IC REG LDO 5V 0.8A SOT223; Internal_Part_Number: MCD-00088; Manufacturer_Part_Number: LD1117S50TR; Manufacturer: STMICROELECTRONICS; ECCN_US: EAR99; ECCN_EU: NEC; Provided_By: Subcon; Initial_Board_Reference: mb1274

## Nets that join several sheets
AGND: arduino_extension_interfaces (5 pins), mcu (C7.1 C10.1 R11.1)
EXTERN_5V: arduino_extension_interfaces (CN1.6), power (JP4.5)
EXTERN_VLCD: arduino_extension_interfaces (R27.1), mcu (5 pins)
GND: hed_link (22 pins), arduino_extension_interfaces (10 pins), mcu (28 pins), power (12 pins)
PA0: arduino_extension_interfaces (C33.2 CN6.34 R26.1), mcu (C7.2 C10.2 R3.1 U1.9)
VBAT: arduino_extension_interfaces (CN1.33), mcu (R2.2), power (R34.1)
VBUS_5V: hed_link (9 pins), arduino_extension_interfaces (CN6.10), power (JP4.1)
VCC_3V3: arduino_extension_interfaces (CN1.12 CN1.16 CN2.2 CN2.4), mcu (R4.2 R12.2), power (JP5.1)
VCC_5V: arduino_extension_interfaces (CN1.18 CN2.5), power (6 pins)
VCC_MCU: hed_link (P1.1 R31.1), arduino_extension_interfaces (CN1.5), mcu (10 pins), power (JP6.1)
VIN: arduino_extension_interfaces (CN1.24 CN2.8), power (C23.2 U4.3)
VIN_5V: arduino_extension_interfaces (R24.1), power (C25.2 JP4.3 U4.2)
MCU_NRST: hed_link (R49.1), mcu (R54.1)
MCU_SWCLK: hed_link (R47.1), mcu (R52.1)
MCU_SWDIO: hed_link (R48.1), mcu (R53.1)
NRST: arduino_extension_interfaces (CN1.14 CN2.3), mcu (5 pins)
PA1: arduino_extension_interfaces (CN1.28 CN3.1), mcu (U1.16)
PA2: arduino_extension_interfaces (CN1.30 CN3.2), mcu (U1.17)
PA3: arduino_extension_interfaces (CN1.32 CN3.3), mcu (U1.18)
PA4: arduino_extension_interfaces (CN1.34 CN3.4), mcu (U1.23)
PA5: arduino_extension_interfaces (CN4.6 CN6.11), mcu (U1.24)
PA6: arduino_extension_interfaces (CN4.5 CN6.13), mcu (D1.2 U1.25)
PA7: arduino_extension_interfaces (CN4.4 CN6.15), mcu (D2.2 U1.26)
PA8: arduino_extension_interfaces (CN5.8 CN6.23), mcu (U1.36)
PA9: arduino_extension_interfaces (CN4.1 CN6.21), mcu (U1.37)
PA10: arduino_extension_interfaces (CN5.3 CN6.33), mcu (U1.45)
PA11: hed_link (R39.2), arduino_extension_interfaces (CN5.2 CN6.35), mcu (U1.46)
PA12: hed_link (R40.2), arduino_extension_interfaces (CN5.1 CN6.37), mcu (U1.47)
PA13: arduino_extension_interfaces (CN1.7), mcu (R53.2 U1.48)
PA14: arduino_extension_interfaces (CN1.8), mcu (R52.2 U1.49)
PA15: arduino_extension_interfaces (CN1.10), mcu (U1.51)
PB0: arduino_extension_interfaces (CN4.3 CN6.17), mcu (C13.1 U1.27)
PB1: arduino_extension_interfaces (CN4.2 CN6.19), mcu (C14.1 U1.28)
PB2: arduino_extension_interfaces (CN6.24), mcu (C15.1 U1.29)
PB3: arduino_extension_interfaces (CN5.4 CN6.31), mcu (U1.54)
PB4: arduino_extension_interfaces (CN5.5 CN6.29), mcu (U1.55)
PB5: arduino_extension_interfaces (CN5.6 CN6.27), mcu (U1.56)
PB6: arduino_extension_interfaces (CN6.22), mcu (U1.57)
PB7: arduino_extension_interfaces (CN1.21), mcu (U1.58)
PB8: arduino_extension_interfaces (CN4.10 CN6.3 R22.1), mcu (U1.59)
PB9: arduino_extension_interfaces (CN4.9 CN6.5 R23.1), mcu (U1.60)
PB10: arduino_extension_interfaces (R20.2), mcu (U1.30)
PB11: arduino_extension_interfaces (R21.2), mcu (U1.31)
PB12: arduino_extension_interfaces (CN6.30), mcu (U1.32)
PB13: arduino_extension_interfaces (CN6.28), mcu (U1.33)
PB14: arduino_extension_interfaces (CN5.7 CN6.25), mcu (U1.34)
PB15: arduino_extension_interfaces (CN6.26), mcu (U1.35)
PC0: arduino_extension_interfaces (CN6.12), mcu (U1.13)
PC1: arduino_extension_interfaces (CN6.14), mcu (U1.14)
PC2: arduino_extension_interfaces (CN1.35), mcu (U1.15)
PC3: arduino_extension_interfaces (CN6.16), mcu (U1.19)
PC4: arduino_extension_interfaces (CN6.18), mcu (U1.20)
PC5: arduino_extension_interfaces (CN1.37), mcu (U1.21)
PC6: arduino_extension_interfaces (CN6.4), mcu (U1.22)
PC7: arduino_extension_interfaces (CN6.6), mcu (U1.38)
PC8: arduino_extension_interfaces (CN6.2), mcu (U1.39)
PC9: arduino_extension_interfaces (CN6.1), mcu (JP1.1 U1.50)
PC10: arduino_extension_interfaces (CN1.3), mcu (U1.52)
PC11: arduino_extension_interfaces (CN1.4), mcu (U1.53)
PC12: arduino_extension_interfaces (CN1.1), mcu (U1.1)
PC13: arduino_extension_interfaces (CN1.23), mcu (R6.1 U1.2)
PC14: arduino_extension_interfaces (R17.2), mcu (R7.1 U1.3)
PC15: arduino_extension_interfaces (R16.2), mcu (R8.1 U1.4)
PD0: arduino_extension_interfaces (CN1.13), mcu (U1.40)
PD1: arduino_extension_interfaces (CN1.11), mcu (U1.41)
PD2: arduino_extension_interfaces (CN1.2), mcu (U1.61)
PD3: arduino_extension_interfaces (CN1.15), mcu (U1.62)
PD4: arduino_extension_interfaces (CN1.17), mcu (U1.63)
PD5: arduino_extension_interfaces (CN1.26), mcu (U1.64)
PF0: arduino_extension_interfaces (R19.2), mcu (R9.2 U1.11)
PF1: arduino_extension_interfaces (R18.2), mcu (R10.2 U1.12)

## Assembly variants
None: all parts fitted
